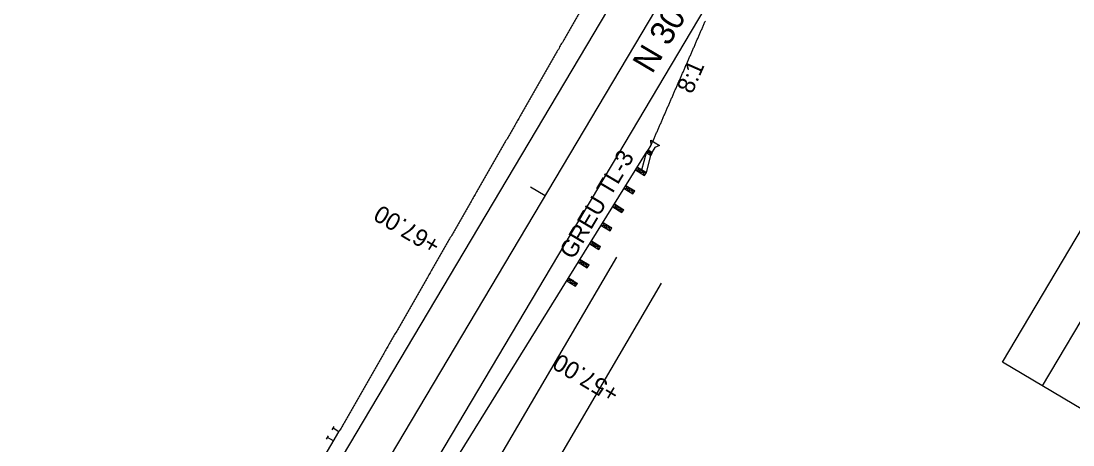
# Model space of a CAD drawing. Extents: x 2138032 to 2141863, y 405316 to 411953.
# Drawn here: x 2140967.3 to 2141272, y 410400.8 to 410523.7 of the extents above; entities that cross this region are included whole.
import ezdxf

# ---------------------------------------------------------------- set-up
doc = ezdxf.new("R2010")
doc.units = 0
for name, color, linetype in [('Prop Dimension Text', 7, 'Continuous'), ('Prop EOT', 7, 'Continuous'), ('Prop Guardrail', 7, 'Continuous'), ('Prop Guardrail Anchor Unit CELL', 7, 'Continuous'), ('Prop Horizontal Alignment', 7, 'Continuous'), ('Prop Horizontal Alignment Curve and Spiral Data', 7, 'Continuous'), ('Prop Horizontal Alignment Direction Label', 7, 'Continuous'), ('Prop Horizontal Alignment Tick Small', 7, 'Continuous'), ('Prop Paved Shoulder', 7, 'Continuous'), ('Prop Structure Anchor Unit CELL', 7, 'Continuous'), ('Scratch_Level_3', 7, 'Continuous')]:
    doc.layers.add(name, color=color, linetype=linetype)

msp = doc.modelspace()

# ---------------------------------------------------------------- linework, layer by layer
at = {"layer": 'Prop EOT'}
for p, q in [((2140946.62, 410205.9), (2141250.61, 410718.06)), ((2140967.26, 410193.65), (2141271.25, 410705.81))]:
    msp.add_line(p, q, dxfattribs=at)
at = {"layer": 'Prop Guardrail'}
msp.add_line((2141087.74, 410387.81), (2141124.01, 410446.23), dxfattribs=at)
for points in [[(2141145.62, 410555.13), (2141145.24, 410554.46), (2141144.85, 410553.78), (2141144.46, 410553.1), (2141144.07, 410552.42), (2141143.68, 410551.75), (2141143.29, 410551.07), (2141142.9, 410550.39), (2141142.52, 410549.71), (2141142.13, 410549.03), (2141141.74, 410548.36), (2141141.35, 410547.68), (2141140.96, 410547), (2141140.57, 410546.32), (2141140.18, 410545.64), (2141139.8, 410544.97), (2141139.41, 410544.29), (2141139.02, 410543.61), (2141138.63, 410542.93), (2141138.24, 410542.26), (2141137.85, 410541.58), (2141137.46, 410540.9), (2141137.08, 410540.22), (2141136.69, 410539.54), (2141136.3, 410538.87), (2141135.91, 410538.19), (2141135.52, 410537.51), (2141135.13, 410536.83), (2141134.74, 410536.15), (2141134.36, 410535.48), (2141133.97, 410534.8), (2141133.58, 410534.12), (2141133.19, 410533.44), (2141132.8, 410532.77), (2141132.41, 410532.09), (2141132.02, 410531.41), (2141131.64, 410530.73), (2141131.25, 410530.05), (2141130.86, 410529.38), (2141130.47, 410528.7), (2141130.08, 410528.02), (2141129.69, 410527.34), (2141129.3, 410526.66), (2141128.92, 410525.99), (2141128.53, 410525.31), (2141128.14, 410524.63), (2141127.75, 410523.95), (2141127.36, 410523.28), (2141126.97, 410522.6), (2141126.58, 410521.92), (2141126.2, 410521.24), (2141125.81, 410520.56), (2141125.42, 410519.89), (2141125.03, 410519.21), (2141124.64, 410518.53), (2141124.25, 410517.85), (2141123.86, 410517.17), (2141123.47, 410516.5), (2141123.09, 410515.82), (2141122.7, 410515.14), (2141122.31, 410514.46), (2141121.92, 410513.79), (2141121.53, 410513.11), (2141121.14, 410512.43), (2141120.75, 410511.75), (2141120.37, 410511.07), (2141119.98, 410510.4), (2141119.59, 410509.72), (2141119.2, 410509.04), (2141118.81, 410508.36), (2141118.42, 410507.68), (2141118.03, 410507.01), (2141117.65, 410506.33), (2141117.26, 410505.65), (2141116.87, 410504.97)], [(2141116.87, 410504.97), (2141116.48, 410504.3), (2141116.09, 410503.62), (2141115.7, 410502.94), (2141115.31, 410502.26), (2141114.93, 410501.58), (2141114.54, 410500.91), (2141114.15, 410500.23), (2141113.76, 410499.55), (2141113.37, 410498.87), (2141112.98, 410498.19), (2141112.59, 410497.52), (2141112.21, 410496.84), (2141111.82, 410496.16), (2141111.43, 410495.48), (2141111.04, 410494.81), (2141110.65, 410494.13), (2141110.26, 410493.45), (2141109.87, 410492.77), (2141109.49, 410492.09), (2141109.1, 410491.42), (2141108.71, 410490.74), (2141108.32, 410490.06), (2141107.93, 410489.38), (2141107.54, 410488.7), (2141107.15, 410488.03), (2141106.77, 410487.35), (2141106.38, 410486.67), (2141105.99, 410485.99), (2141105.6, 410485.32), (2141105.21, 410484.64), (2141104.82, 410483.96), (2141104.43, 410483.28), (2141104.05, 410482.6), (2141103.66, 410481.93), (2141103.27, 410481.25), (2141102.88, 410480.57), (2141102.49, 410479.89), (2141102.1, 410479.21), (2141101.71, 410478.54), (2141101.33, 410477.86), (2141100.94, 410477.18), (2141100.55, 410476.5), (2141100.16, 410475.83), (2141099.77, 410475.15), (2141099.38, 410474.47), (2141098.99, 410473.79), (2141098.61, 410473.11), (2141098.22, 410472.44), (2141097.83, 410471.76), (2141097.44, 410471.08), (2141097.05, 410470.4), (2141096.66, 410469.72), (2141096.27, 410469.05), (2141095.89, 410468.37), (2141095.5, 410467.69), (2141095.11, 410467.01), (2141094.72, 410466.34), (2141094.33, 410465.66), (2141093.94, 410464.98), (2141093.55, 410464.3), (2141093.17, 410463.62), (2141092.78, 410462.95), (2141092.39, 410462.27), (2141092, 410461.59), (2141091.61, 410460.91), (2141091.22, 410460.23), (2141090.83, 410459.56), (2141090.45, 410458.88), (2141090.06, 410458.2), (2141089.67, 410457.52), (2141089.28, 410456.85), (2141088.89, 410456.17), (2141088.5, 410455.49), (2141088.11, 410454.81)], [(2141088.11, 410454.81), (2141087.73, 410454.13), (2141087.34, 410453.46), (2141086.95, 410452.78), (2141086.56, 410452.1), (2141086.17, 410451.42), (2141085.78, 410450.74), (2141085.39, 410450.07), (2141085.01, 410449.39), (2141084.62, 410448.71), (2141084.23, 410448.03), (2141083.84, 410447.36), (2141083.45, 410446.68), (2141083.06, 410446), (2141082.67, 410445.32), (2141082.28, 410444.64), (2141081.9, 410443.97), (2141081.51, 410443.29), (2141081.12, 410442.61), (2141080.73, 410441.93), (2141080.34, 410441.25), (2141079.95, 410440.58), (2141079.56, 410439.9), (2141079.18, 410439.22), (2141078.79, 410438.54), (2141078.4, 410437.87), (2141078.01, 410437.19), (2141077.62, 410436.51), (2141077.23, 410435.83), (2141076.84, 410435.15), (2141076.46, 410434.48), (2141076.07, 410433.8), (2141075.68, 410433.12), (2141075.29, 410432.44), (2141074.9, 410431.76), (2141074.51, 410431.09), (2141074.12, 410430.41), (2141073.74, 410429.73), (2141073.35, 410429.05), (2141072.96, 410428.38), (2141072.57, 410427.7), (2141072.18, 410427.02), (2141071.79, 410426.34), (2141071.4, 410425.66), (2141071.02, 410424.99), (2141070.63, 410424.31), (2141070.24, 410423.63), (2141069.85, 410422.95), (2141069.46, 410422.27), (2141069.07, 410421.6), (2141068.68, 410420.92), (2141068.3, 410420.24), (2141067.91, 410419.56), (2141067.52, 410418.89), (2141067.13, 410418.21), (2141066.74, 410417.53), (2141066.35, 410416.85), (2141065.96, 410416.17), (2141065.58, 410415.5), (2141065.19, 410414.82), (2141064.8, 410414.14), (2141064.41, 410413.46), (2141064.02, 410412.78), (2141063.63, 410412.11), (2141063.24, 410411.43), (2141062.86, 410410.75), (2141062.47, 410410.07), (2141062.08, 410409.4), (2141061.69, 410408.72), (2141061.3, 410408.04), (2141060.91, 410407.36), (2141060.52, 410406.68), (2141060.14, 410406.01), (2141059.75, 410405.33), (2141059.36, 410404.65)]]:
    msp.add_spline(points, degree=3, dxfattribs=at)
at = {"layer": 'Prop Guardrail Anchor Unit CELL'}
for p, q in [((2141149.78, 410487.7), (2141149.64, 410489.15)), ((2141149.64, 410489.15), (2141152.17, 410487.65)), ((2141124.01, 410446.23), (2141148.65, 410485.95)), ((2141147.11, 410480.56), (2141148.39, 410485.53)), ((2141150.19, 410485.59), (2141148.39, 410485.53)), ((2141148.39, 410485.53), (2141149.67, 410484.74)), ((2141148.74, 410485.94), (2141149.78, 410487.7)), ((2141149.26, 410485.63), (2141148.74, 410485.94)), ((2141148.92, 410486.38), (2141150.19, 410485.59)), ((2141148.92, 410486.38), (2141149.67, 410484.74)), ((2141149.78, 410485.31), (2141149.26, 410485.63)), ((2141149.67, 410484.74), (2141150.19, 410485.59)), ((2141150.83, 410487.07), (2141149.78, 410485.31)), ((2141152.17, 410487.65), (2141150.83, 410487.07)), ((2141148.41, 410479.75), (2141149.67, 410484.74)), ((2141149.67, 410484.74), (2141149.93, 410485.16)), ((2141145.28, 410480.51), (2141147.11, 410480.56)), ((2141145.28, 410480.51), (2141147.88, 410478.9)), ((2141145.81, 410481.36), (2141148.41, 410479.75)), ((2141146.58, 410479.71), (2141145.81, 410481.36)), ((2141146.58, 410479.71), (2141147.11, 410480.56)), ((2141148.41, 410479.75), (2141146.58, 410479.71)), ((2141147.11, 410480.56), (2141147.88, 410478.9)), ((2141147.88, 410478.9), (2141148.41, 410479.75)), ((2141141.96, 410475.16), (2141143.76, 410475.22)), ((2141141.96, 410475.16), (2141144.51, 410473.58)), ((2141142.49, 410476.01), (2141145.03, 410474.43)), ((2141143.23, 410474.37), (2141142.49, 410476.01)), ((2141143.23, 410474.37), (2141143.76, 410475.22)), ((2141145.03, 410474.43), (2141143.23, 410474.37)), ((2141143.76, 410475.22), (2141144.51, 410473.58)), ((2141144.51, 410473.58), (2141145.03, 410474.43)), ((2141139.16, 410470.65), (2141141.83, 410469)), ((2141139.97, 410468.98), (2141139.16, 410470.65)), ((2141138.64, 410469.8), (2141140.5, 410469.83)), ((2141138.64, 410469.8), (2141141.3, 410468.15)), ((2141139.97, 410468.98), (2141140.5, 410469.83)), ((2141141.83, 410469), (2141139.97, 410468.98)), ((2141140.5, 410469.83), (2141141.3, 410468.15)), ((2141141.3, 410468.15), (2141141.83, 410469)), ((2141135.31, 410464.45), (2141135.84, 410465.3)), ((2141135.31, 410464.45), (2141137.13, 410464.5)), ((2141135.31, 410464.45), (2141137.89, 410462.85)), ((2141135.84, 410465.3), (2141138.42, 410463.7)), ((2141136.6, 410463.65), (2141135.84, 410465.3)), ((2141136.6, 410463.65), (2141137.13, 410464.5)), ((2141137.13, 410464.5), (2141137.89, 410462.85)), ((2141138.42, 410463.7), (2141136.6, 410463.65)), ((2141137.89, 410462.85), (2141138.42, 410463.7)), ((2141131.99, 410459.1), (2141133.82, 410459.14)), ((2141131.99, 410459.1), (2141134.58, 410457.49)), ((2141132.52, 410459.94), (2141135.11, 410458.34)), ((2141133.29, 410458.29), (2141132.52, 410459.94)), ((2141133.29, 410458.29), (2141133.82, 410459.14)), ((2141135.11, 410458.34), (2141133.29, 410458.29)), ((2141133.82, 410459.14), (2141134.58, 410457.49)), ((2141134.58, 410457.49), (2141135.11, 410458.34)), ((2141128.67, 410453.74), (2141130.5, 410453.79)), ((2141128.67, 410453.74), (2141131.26, 410452.13)), ((2141129.2, 410454.59), (2141131.79, 410452.98)), ((2141129.97, 410452.94), (2141129.2, 410454.59)), ((2141129.97, 410452.94), (2141130.5, 410453.79)), ((2141131.79, 410452.98), (2141129.97, 410452.94)), ((2141130.5, 410453.79), (2141131.26, 410452.13)), ((2141131.26, 410452.13), (2141131.79, 410452.98)), ((2141125.35, 410448.39), (2141125.88, 410449.24)), ((2141125.88, 410449.24), (2141128.43, 410447.65)), ((2141125.88, 410449.24), (2141127.15, 410448.44)), ((2141126.62, 410447.59), (2141125.88, 410449.24)), ((2141127.15, 410448.44), (2141125.35, 410448.39)), ((2141125.35, 410448.39), (2141127.9, 410446.8)), ((2141126.62, 410447.59), (2141127.15, 410448.44)), ((2141128.43, 410447.65), (2141126.62, 410447.59)), ((2141127.15, 410448.44), (2141127.9, 410446.8)), ((2141127.9, 410446.8), (2141128.43, 410447.65))]:
    msp.add_line(p, q, dxfattribs=at)
at = {"layer": 'Prop Horizontal Alignment'}
msp.add_line((2140956.94, 410199.77), (2141260.93, 410711.93), dxfattribs=at)
at = {"layer": 'Prop Horizontal Alignment Curve and Spiral Data'}
msp.add_line((2141263.11, 410417.95), (2141321.34, 410516.04), dxfattribs=at)
msp.add_lwpolyline([(2141251.53, 410424.83), (2141309.75, 410522.92), (2141400.27, 410469.2), (2141342.04, 410371.1)], close=True, dxfattribs=at)
at = {"layer": 'Prop Horizontal Alignment Tick Small'}
msp.add_line((2141119.1, 410472.98), (2141114.8, 410475.53), dxfattribs=at)
at = {"layer": 'Prop Paved Shoulder'}
msp.add_spline([(2141149.78, 410487.7), (2141149.99, 410488.19), (2141150.21, 410488.67), (2141150.42, 410489.16), (2141150.63, 410489.64), (2141150.84, 410490.13), (2141151.06, 410490.62), (2141151.27, 410491.1), (2141151.48, 410491.59), (2141151.69, 410492.08), (2141151.9, 410492.56), (2141152.12, 410493.05), (2141152.33, 410493.54), (2141152.54, 410494.02), (2141152.75, 410494.51), (2141152.96, 410494.99), (2141153.18, 410495.48), (2141153.39, 410495.97), (2141153.6, 410496.45), (2141153.81, 410496.94), (2141154.03, 410497.43), (2141154.24, 410497.91), (2141154.45, 410498.4), (2141154.66, 410498.89), (2141154.87, 410499.37), (2141155.09, 410499.86), (2141155.3, 410500.34), (2141155.51, 410500.83), (2141155.72, 410501.32), (2141155.93, 410501.8), (2141156.15, 410502.29), (2141156.36, 410502.78), (2141156.57, 410503.26), (2141156.78, 410503.75), (2141157, 410504.23), (2141157.21, 410504.72), (2141157.42, 410505.21), (2141157.63, 410505.69), (2141157.84, 410506.18), (2141158.06, 410506.67), (2141158.27, 410507.15), (2141158.48, 410507.64), (2141158.69, 410508.13), (2141158.9, 410508.61), (2141159.12, 410509.1), (2141159.33, 410509.58), (2141159.54, 410510.07), (2141159.75, 410510.56), (2141159.96, 410511.04), (2141160.18, 410511.53), (2141160.39, 410512.02), (2141160.6, 410512.5), (2141160.81, 410512.99), (2141161.03, 410513.48), (2141161.24, 410513.96), (2141161.45, 410514.45), (2141161.66, 410514.93), (2141161.87, 410515.42), (2141162.09, 410515.91), (2141162.3, 410516.39), (2141162.51, 410516.88), (2141162.72, 410517.37), (2141162.93, 410517.85), (2141163.15, 410518.34), (2141163.36, 410518.82), (2141163.57, 410519.31), (2141163.78, 410519.8), (2141164, 410520.28), (2141164.21, 410520.77), (2141164.42, 410521.26), (2141164.63, 410521.74), (2141164.84, 410522.23), (2141165.06, 410522.72), (2141165.48, 410523.69)], degree=3, dxfattribs=at)
at = {"layer": 'Prop Structure Anchor Unit CELL'}
for p, q in [((2141057.35, 410405.18), (2141057.93, 410406.16)), ((2141049.79, 410388.53), (2141059.36, 410404.65)), ((2141055.75, 410402.49), (2141056.34, 410403.48)), ((2141057.76, 410401.96), (2141056.04, 410402.98)), ((2141059.36, 410404.65), (2141057.64, 410405.67))]:
    msp.add_line(p, q, dxfattribs=at)
at = {"layer": 'Scratch_Level_3'}
for p, q in [((2141139.73, 410455.24), (2140992.96, 410204.62)), ((2141152.68, 410447.66), (2141005.91, 410197.04))]:
    msp.add_line(p, q, dxfattribs=at)

# ---------------------------------------------------------------- texts
at = {"layer": 'Prop Dimension Text'}
for s, rotation, p in [('8:1', 66.4348, (2141161.61, 410502.31)), ('+67.00', 149.3093, (2141089.21, 410460.04)), ('+57.00', 149.3093, (2141141.03, 410416.98))]:
    msp.add_text(s, height=5, rotation=rotation, dxfattribs=at).set_placement(p)
at = {"layer": 'Prop Guardrail Anchor Unit CELL'}
msp.add_text('GREU TL-3', height=5, rotation=59.3093, dxfattribs=at).set_placement((2141127.2, 410454.31))
at = {"layer": 'Prop Horizontal Alignment Direction Label'}
msp.add_text('N 30%%d 41\' 26.7" E', height=7, rotation=59.3093, dxfattribs=at).set_placement((2141150.05, 410508.13))

doc.saveas('drawing.dxf')
